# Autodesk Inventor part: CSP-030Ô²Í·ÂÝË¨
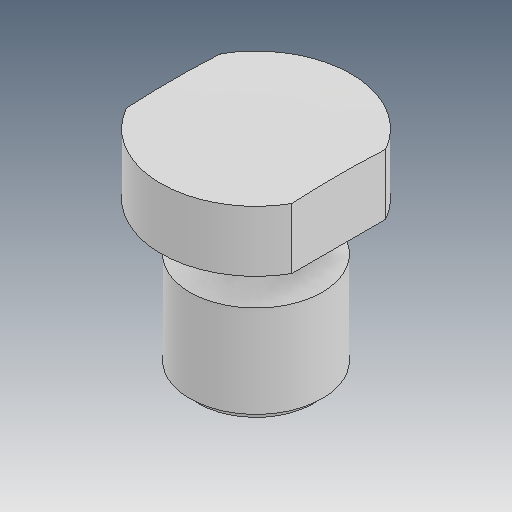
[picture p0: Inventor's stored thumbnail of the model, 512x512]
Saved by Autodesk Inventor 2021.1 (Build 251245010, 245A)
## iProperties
Created: 2019-01
Part Number: CSP-030Ô²Í·ÂÝË¨
Material: Ogólny
Document SubType Name: Modeling
Designer: user
Density: 1 g/cm^3
Appearance: Domyślna
Author: user
Revision Number: ÈÎºÎ
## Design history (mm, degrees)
feature "ÇÐ³ý-À­Éì1"
node "Bryła1"
